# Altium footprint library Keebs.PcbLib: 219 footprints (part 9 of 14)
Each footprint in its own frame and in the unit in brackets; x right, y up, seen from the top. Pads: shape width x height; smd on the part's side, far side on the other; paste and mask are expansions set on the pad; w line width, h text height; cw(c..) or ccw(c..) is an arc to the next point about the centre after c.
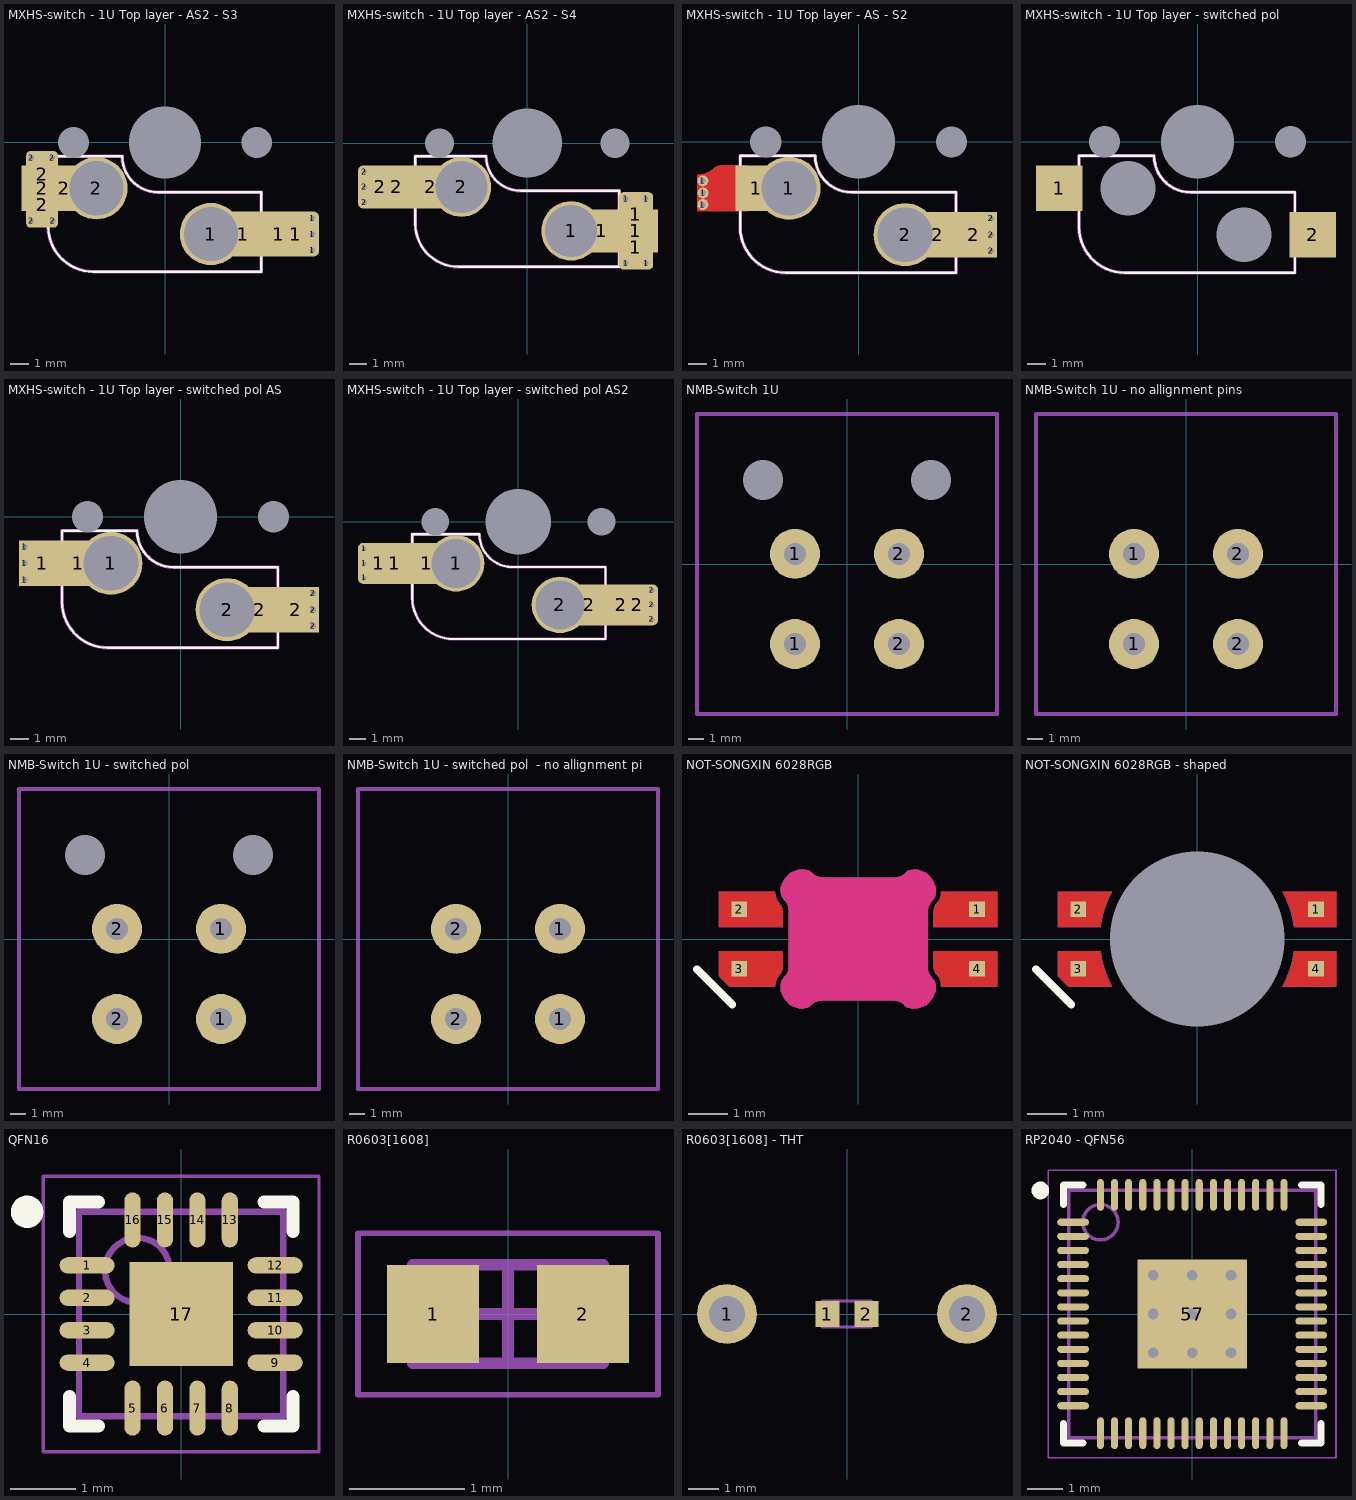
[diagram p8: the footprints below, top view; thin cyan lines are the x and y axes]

## MXHS-switch - 1U Top layer - AS2 - S3 [mm]
pads (19):
  round 3.45 hole 3 mask+0: 1(2.54,-5.08) 2(-3.81,-2.54)
  rect 2.55x2.5 smd paste-40 mask+0.102: 1(4.318,-5.08) 2(-5.588,-2.54)
  rect 2.55x2.5 smd: 1(6.29,-5.08)
  rrect25% 2.55x2.5 smd paste-40 mask+0.102: 1(7.25,-5.08)
  round 0.6 hole 0.3 mask+0.102: 1(8.15,-5.969) 1(8.15,-5.08) 1(8.15,-4.191) 2(-7.412,-4.349) 2(-7.412,-0.858) 2(-6.25,-0.858) 2(-6.234,-4.349)
  rrect25% 1.75x2.55 smd paste-40 mask+0.102: 2(-6.823,-3.449) 2(-6.823,-1.758)
  rect 2.3x2.5 smd: 2(-6.8,-2.54)
  round 1 hole 1.7 unplated: ""(-5.08,0) ""(5.08,0)
  round 1 hole 4 unplated: ""(0,0)
Top Overlay:
  lines w0.127: -6.481,-4.662 ccw(c-3.981,-4.662) -3.981,-7.162 5.319,-7.162 5.319,-2.762 -0.381,-2.762 cw(c-0.381,-0.762) -2.381,-0.762 -6.481,-0.762 -6.481,-4.662
Mechanical 13:
  lines w0.1: -0.5,0 0.5,0 ; 0,-0.5 0,0.5
  lines w0.2: -6.481,-4.662 ccw(c-3.981,-4.662) -3.981,-7.162 5.319,-7.162 5.319,-2.762 -0.381,-2.762 cw(c-0.381,-0.762) -2.381,-0.762 -6.481,-0.762 -6.481,-4.662
  text ".Designator" at 3.048,-4.826 h0.7
Mechanical 15:
  lines w0.1: -1.77,0 -0.77,0 ; 0,-0.5 0,0.5
  lines w0.127: -6.481,-4.662 ccw(c-3.981,-4.662) -3.981,-7.162 5.319,-7.162 5.319,-2.762 -0.381,-2.762 cw(c-0.381,-0.762) -2.381,-0.762 -6.481,-0.762 -6.481,-4.662
3D body "kailh_socket_mx.stp": height -0.35, standoff -3.4, extent -7.9,-6.745 6.6,-0.855

## MXHS-switch - 1U Top layer - AS2 - S4 [mm]
pads (19):
  round 3.45 hole 3 mask+0: 1(2.54,-5.08) 2(-3.81,-2.54)
  rect 2.55x2.5 smd paste-40 mask+0.102: 1(4.318,-5.08) 2(-5.588,-2.54)
  round 0.6 hole 0.3 mask+0.102: 1(5.701,-6.94) 1(5.701,-3.22) 1(6.879,-6.94) 1(6.879,-3.22) 2(-9.42,-3.429) 2(-9.42,-2.54) 2(-9.42,-1.651)
  rrect25% 2x2.55 smd paste-40 mask+0.102: 1(6.29,-6.04) 1(6.29,-4.12)
  rect 2.55x2.5 smd: 1(6.29,-5.08) 2(-7.56,-2.54)
  rrect25% 2.55x2.5 smd paste-40 mask+0.102: 2(-8.52,-2.54)
  round 1 hole 1.7 unplated: ""(-5.08,0) ""(5.08,0)
  round 1 hole 4 unplated: ""(0,0)
Top Overlay:
  lines w0.127: -6.481,-4.662 ccw(c-3.981,-4.662) -3.981,-7.162 5.319,-7.162 5.319,-2.762 -0.381,-2.762 cw(c-0.381,-0.762) -2.381,-0.762 -6.481,-0.762 -6.481,-4.662
Mechanical 13:
  lines w0.1: -0.5,0 0.5,0 ; 0,-0.5 0,0.5
  lines w0.2: -6.481,-4.662 ccw(c-3.981,-4.662) -3.981,-7.162 5.319,-7.162 5.319,-2.762 -0.381,-2.762 cw(c-0.381,-0.762) -2.381,-0.762 -6.481,-0.762 -6.481,-4.662
  text ".Designator" at 3.048,-4.826 h0.7
Mechanical 15:
  lines w0.1: -1.77,0 -0.77,0 ; 0,-0.5 0,0.5
  lines w0.127: -6.481,-4.662 ccw(c-3.981,-4.662) -3.981,-7.162 5.319,-7.162 5.319,-2.762 -0.381,-2.762 cw(c-0.381,-0.762) -2.381,-0.762 -6.481,-0.762 -6.481,-4.662
3D body "kailh_socket_mx.stp": height -0.35, standoff -3.4, extent -7.9,-6.745 6.6,-0.855

## MXHS-switch - 1U Top layer - AS - S2 [mm] "Adjusted footprint to prevent conflict with tray mount mounting hole"
pads (14):
  round 0.6 hole 0.3 mask+0.102: 1(-8.52,-3.429) 1(-8.52,-2.134) 1(-8.509,-2.794) 2(7.25,-5.969) 2(7.25,-5.08) 2(7.25,-4.191)
  rect 2.3x2.492 smd paste-40 mask+0.102: 1(-5.588,-2.54)
  round 3.45 hole 3 mask+0: 1(-3.81,-2.54) 2(2.54,-5.08)
  rect 2.55x2.5 smd paste-40 mask+0.102: 2(4.318,-5.08)
  rect 2.55x2.5 smd: 2(6.29,-5.08)
  round 1 hole 1.7 unplated: ""(-5.08,0) ""(5.08,0)
  round 1 hole 4 unplated: ""(0,0)
Top Layer:
  region: -6.096,-1.295 -6.096,-3.785 -8.839,-3.785 -8.839,-1.905 -8.839,-1.88 -8.82,-1.833 -8.784,-1.797 -8.737,-1.778 -8.712,-1.778 -8.606,-1.773 -8.398,-1.731 -8.201,-1.65 -8.025,-1.532 -7.946,-1.46 -7.906,-1.421 -7.814,-1.36 -7.712,-1.317 -7.603,-1.295 -7.547,-1.295
Top Overlay:
  lines w0.127: -6.481,-4.662 ccw(c-3.981,-4.662) -3.981,-7.162 5.319,-7.162 5.319,-2.762 -0.381,-2.762 cw(c-0.381,-0.762) -2.381,-0.762 -6.481,-0.762 -6.481,-4.662
Mechanical 13:
  lines w0.1: -0.5,0 0.5,0 ; 0,-0.5 0,0.5
  lines w0.2: -6.481,-4.662 ccw(c-3.981,-4.662) -3.981,-7.162 5.319,-7.162 5.319,-2.762 -0.381,-2.762 cw(c-0.381,-0.762) -2.381,-0.762 -6.481,-0.762 -6.481,-4.662
  text ".Designator" at 3.048,-4.826 h0.7
Mechanical 15:
  lines w0.1: -1.77,0 -0.77,0 ; 0,-0.5 0,0.5
  lines w0.127: -6.481,-4.662 ccw(c-3.981,-4.662) -3.981,-7.162 5.319,-7.162 5.319,-2.762 -0.381,-2.762 cw(c-0.381,-0.762) -2.381,-0.762 -6.481,-0.762 -6.481,-4.662
3D body "kailh_socket_mx.stp": height -0.35, standoff -3.4, extent -7.9,-6.745 6.6,-0.855

## MXHS-switch - 1U Top layer - switched pol [mm]
pads (7):
  rect 2.55x2.5 smd: 1(-7.56,-2.54) 2(6.29,-5.08)
  round 1 hole 1.7 unplated: ""(-5.08,0) ""(5.08,0)
  round 0 hole 3 unplated: ""(-3.81,-2.54) ""(2.54,-5.08)
  round 1 hole 4 unplated: ""(0,0)
Top Overlay:
  lines w0.127: -6.481,-4.662 ccw(c-3.981,-4.662) -3.981,-7.162 5.319,-7.162 5.319,-2.762 -0.381,-2.762 cw(c-0.381,-0.762) -2.381,-0.762 -6.481,-0.762 -6.481,-4.662
Mechanical 13:
  lines w0.1: -0.5,0 0.5,0 ; 0,-0.5 0,0.5
  lines w0.2: -6.481,-4.662 ccw(c-3.981,-4.662) -3.981,-7.162 5.319,-7.162 5.319,-2.762 -0.381,-2.762 cw(c-0.381,-0.762) -2.381,-0.762 -6.481,-0.762 -6.481,-4.662
  text ".Designator" at 3.048,-4.826 h0.7
Mechanical 15:
  lines w0.1: -1.77,0 -0.77,0 ; 0,-0.5 0,0.5
  lines w0.127: -6.481,-4.662 ccw(c-3.981,-4.662) -3.981,-7.162 5.319,-7.162 5.319,-2.762 -0.381,-2.762 cw(c-0.381,-0.762) -2.381,-0.762 -6.481,-0.762 -6.481,-4.662
3D body "kailh_socket_mx.stp": height -0.35, standoff -3.4, extent -7.9,-6.745 6.6,-0.855

## MXHS-switch - 1U Top layer - switched pol AS [mm]
pads (15):
  round 0.6 hole 0.3 mask+0.102: 1(-8.52,-3.429) 1(-8.52,-2.54) 1(-8.52,-1.651) 2(7.25,-5.969) 2(7.25,-5.08) 2(7.25,-4.191)
  rect 2.55x2.5 smd: 1(-7.56,-2.54) 2(6.29,-5.08)
  rect 2.55x2.5 smd paste-40 mask+0.102: 1(-5.588,-2.54) 2(4.318,-5.08)
  round 3.45 hole 3 mask+0: 1(-3.81,-2.54) 2(2.54,-5.08)
  round 1 hole 1.7 unplated: ""(-5.08,0) ""(5.08,0)
  round 1 hole 4 unplated: ""(0,0)
Top Overlay:
  lines w0.127: -6.481,-4.662 ccw(c-3.981,-4.662) -3.981,-7.162 5.319,-7.162 5.319,-2.762 -0.381,-2.762 cw(c-0.381,-0.762) -2.381,-0.762 -6.481,-0.762 -6.481,-4.662
Mechanical 13:
  lines w0.1: -0.5,0 0.5,0 ; 0,-0.5 0,0.5
  lines w0.2: -6.481,-4.662 ccw(c-3.981,-4.662) -3.981,-7.162 5.319,-7.162 5.319,-2.762 -0.381,-2.762 cw(c-0.381,-0.762) -2.381,-0.762 -6.481,-0.762 -6.481,-4.662
  text ".Designator" at 3.048,-4.826 h0.7
Mechanical 15:
  lines w0.1: -1.77,0 -0.77,0 ; 0,-0.5 0,0.5
  lines w0.127: -6.481,-4.662 ccw(c-3.981,-4.662) -3.981,-7.162 5.319,-7.162 5.319,-2.762 -0.381,-2.762 cw(c-0.381,-0.762) -2.381,-0.762 -6.481,-0.762 -6.481,-4.662
3D body "kailh_socket_mx.stp": height -0.35, standoff -3.4, extent -7.9,-6.745 6.6,-0.855

## MXHS-switch - 1U Top layer - switched pol AS2 [mm]
pads (17):
  round 0.6 hole 0.3 mask+0.102: 1(-9.42,-3.429) 1(-9.42,-2.54) 1(-9.42,-1.651) 2(8.15,-5.969) 2(8.15,-5.08) 2(8.15,-4.191)
  rrect25% 2.55x2.5 smd paste-40 mask+0.102: 1(-8.52,-2.54) 2(7.25,-5.08)
  rect 2.55x2.5 smd: 1(-7.56,-2.54) 2(6.29,-5.08)
  rect 2.55x2.5 smd paste-40 mask+0.102: 1(-5.588,-2.54) 2(4.318,-5.08)
  round 3.45 hole 3 mask+0: 1(-3.81,-2.54) 2(2.54,-5.08)
  round 1 hole 1.7 unplated: ""(-5.08,0) ""(5.08,0)
  round 1 hole 4 unplated: ""(0,0)
Top Overlay:
  lines w0.127: -6.481,-4.662 ccw(c-3.981,-4.662) -3.981,-7.162 5.319,-7.162 5.319,-2.762 -0.381,-2.762 cw(c-0.381,-0.762) -2.381,-0.762 -6.481,-0.762 -6.481,-4.662
Mechanical 13:
  lines w0.1: -0.5,0 0.5,0 ; 0,-0.5 0,0.5
  lines w0.2: -6.481,-4.662 ccw(c-3.981,-4.662) -3.981,-7.162 5.319,-7.162 5.319,-2.762 -0.381,-2.762 cw(c-0.381,-0.762) -2.381,-0.762 -6.481,-0.762 -6.481,-4.662
  text ".Designator" at 3.048,-4.826 h0.7
Mechanical 15:
  lines w0.1: -1.77,0 -0.77,0 ; 0,-0.5 0,0.5
  lines w0.127: -6.481,-4.662 ccw(c-3.981,-4.662) -3.981,-7.162 5.319,-7.162 5.319,-2.762 -0.381,-2.762 cw(c-0.381,-0.762) -2.381,-0.762 -6.481,-0.762 -6.481,-4.662
3D body "kailh_socket_mx.stp": height -0.35, standoff -3.4, extent -7.9,-6.745 6.6,-0.855

## NMB-Switch 1U [mm]
pads (7):
  round 3.18 hole 1.4 mask+0.102: 1(-3.3,-5.08) 1(-3.3,0.64) 2(3.3,-5.08) 2(3.3,0.64)
  round 0 hole 2.54 unplated mask+0.102: ""(-5.33,5.33) ""(5.33,5.33)
  round 1 on Mech13: ""(0,0)
Mechanical 13:
  lines w0.254: -9.525,-9.525 -9.525,9.525 9.525,9.525 9.525,-9.525 -9.525,-9.525
  text ".Designator" at -3.575,-3.7 h0.7

## NMB-Switch 1U - no allignment pins [mm]
pads (5):
  round 3.18 hole 1.4 mask+0.102: 1(-3.3,-5.08) 1(-3.3,0.64) 2(3.3,-5.08) 2(3.3,0.64)
  round 1 on Mech13: ""(0,0)
Mechanical 13:
  lines w0.254: -9.525,-9.525 -9.525,9.525 9.525,9.525 9.525,-9.525 -9.525,-9.525
  text ".Designator" at -3.575,-3.7 h0.7

## NMB-Switch 1U - switched pol [mm]
pads (7):
  round 3.18 hole 1.4 mask+0.102: 1(3.3,-5.08) 1(3.3,0.64) 2(-3.3,-5.08) 2(-3.3,0.64)
  round 0 hole 2.54 unplated mask+0.102: ""(-5.33,5.33) ""(5.33,5.33)
  round 1 on Mech13: ""(0,0)
Mechanical 13:
  lines w0.254: -9.525,-9.525 9.525,-9.525 9.525,9.525 -9.525,9.525 -9.525,-9.525
  text ".Designator" at -3.575,-3.7 h0.7

## NMB-Switch 1U - switched pol  - no allignment pins [mm]
pads (5):
  round 3.18 hole 1.4 mask+0.102: 1(3.3,-5.08) 1(3.3,0.64) 2(-3.3,-5.08) 2(-3.3,0.64)
  round 1 on Mech13: ""(0,0)
Mechanical 13:
  lines w0.254: -9.525,-9.525 9.525,-9.525 9.525,9.525 -9.525,9.525 -9.525,-9.525
  text ".Designator" at -3.575,-3.7 h0.7

## NOT-SONGXIN 6028RGB [mm] "Uncommon Anode reverse mount LED"
pads (4):
  rect 0.4x0.4 smd: 1(3,0.75) 2(-3,0.75) 3(-3,-0.75) 4(3,-0.75)
Top Layer:
  region: -3.5,0.304 -3.5,1.195 -2.1,1.195 -2.1,1.172 -2.098,1.13 -2.082,1.048 -2.05,0.97 -2.003,0.901 -1.975,0.869 -1.957,0.852 -1.929,0.81 -1.91,0.763 -1.9,0.714 -1.9,0.688 -1.9,0.304
  region: -3.25,-1.195 -3.5,-0.945 -3.5,-0.304 -1.9,-0.304 -1.9,-0.702 -1.9,-0.727 -1.91,-0.776 -1.929,-0.823 -1.957,-0.865 -1.975,-0.883 -2.003,-0.914 -2.05,-0.984 -2.082,-1.061 -2.098,-1.143 -2.1,-1.185 -2.1,-1.195
  region: 1.975,-0.883 1.957,-0.865 1.929,-0.823 1.91,-0.776 1.9,-0.727 1.9,-0.702 1.9,-0.304 3.5,-0.304 3.5,-1.195 2.1,-1.195 2.1,-1.185 2.098,-1.143 2.082,-1.061 2.05,-0.984 2.003,-0.914
  region: 1.9,0.702 1.9,0.727 1.91,0.776 1.929,0.823 1.957,0.865 1.975,0.883 2.003,0.914 2.05,0.984 2.082,1.061 2.098,1.143 2.1,1.185 2.1,1.195 3.5,1.195 3.5,0.304 1.9,0.304
  pour cut-out: -1.95,-1.2 -1.95,-1.198 -1.95,-1.195 -1.95,-1.192 -1.949,-1.188 -1.949,-1.187 -1.949,-1.185 -1.95,-1.182 -1.95,-1.178 -1.95,-1.175 -1.95,-1.173 -1.95,-1.143 -1.939,-1.085 -1.916,-1.029 -1.882,-0.979 -1.861,-0.958 -1.836,-0.93 -1.794,-0.868 -1.765,-0.798 -1.751,-0.725 -1.749,-0.687 -1.749,0.714 -1.751,0.751 -1.765,0.825 -1.794,0.894 -1.836,0.957 -1.861,0.985 -1.882,1.006 -1.916,1.056 -1.939,1.111 -1.95,1.17 -1.95,1.2 -1.95,1.309 -1.867,1.512 -1.712,1.667 -1.509,1.75 -1.4,1.75 -1.373,1.75 -1.343,1.75 -1.285,1.739 -1.229,1.716 -1.179,1.682 -1.158,1.661 -1.13,1.636 -1.068,1.594 -0.998,1.565 -0.925,1.551 -0.887,1.549 0.914,1.549 0.951,1.551 1.025,1.565 1.094,1.594 1.157,1.636 1.185,1.661 1.206,1.682 1.256,1.716 1.311,1.739 1.37,1.75 1.4,1.75 1.509,1.75 1.712,1.667 1.867,1.512 1.95,1.309 1.95,1.2 1.95,1.198 1.95,1.195 1.95,1.192 1.949,1.188 1.949,1.187 1.949,1.185 1.95,1.182 1.95,1.178 1.95,1.175 1.95,1.173 1.95,1.143 1.939,1.085 1.916,1.029 1.882,0.979 1.861,0.958 1.836,0.93 1.794,0.868 1.765,0.798 1.751,0.725 1.749,0.687 1.749,-0.714 1.751,-0.751 1.765,-0.825 1.794,-0.894 1.836,-0.957 1.861,-0.985 1.882,-1.006 1.916,-1.056 1.939,-1.111 1.95,-1.17 1.95,-1.2 1.95,-1.309 1.867,-1.512 1.712,-1.667 1.509,-1.75 1.4,-1.75 1.398,-1.75 1.395,-1.75 1.392,-1.75 1.388,-1.749 1.387,-1.749 1.385,-1.749 1.382,-1.75 1.378,-1.75 1.375,-1.75 1.373,-1.75 1.343,-1.75 1.285,-1.739 1.229,-1.716 1.179,-1.682 1.158,-1.661 1.13,-1.636 1.068,-1.594 0.998,-1.565 0.925,-1.551 0.887,-1.549 -0.914,-1.549 -0.951,-1.551 -1.025,-1.565 -1.094,-1.594 -1.157,-1.636 -1.185,-1.661 -1.206,-1.682 -1.256,-1.716 -1.311,-1.739 -1.37,-1.75 -1.4,-1.75 -1.509,-1.75 -1.712,-1.667 -1.867,-1.512 -1.95,-1.309
Bottom Layer:
  pour cut-out: -1.95,-1.2 -1.95,-1.198 -1.95,-1.195 -1.95,-1.192 -1.949,-1.188 -1.949,-1.187 -1.949,-1.185 -1.95,-1.182 -1.95,-1.178 -1.95,-1.175 -1.95,-1.173 -1.95,-1.143 -1.939,-1.085 -1.916,-1.029 -1.882,-0.979 -1.861,-0.958 -1.836,-0.93 -1.794,-0.868 -1.765,-0.798 -1.751,-0.725 -1.749,-0.687 -1.749,0.714 -1.751,0.751 -1.765,0.825 -1.794,0.894 -1.836,0.957 -1.861,0.985 -1.882,1.006 -1.916,1.056 -1.939,1.111 -1.95,1.17 -1.95,1.2 -1.95,1.309 -1.867,1.512 -1.712,1.667 -1.509,1.75 -1.4,1.75 -1.373,1.75 -1.343,1.75 -1.285,1.739 -1.229,1.716 -1.179,1.682 -1.158,1.661 -1.13,1.636 -1.068,1.594 -0.998,1.565 -0.925,1.551 -0.887,1.549 0.914,1.549 0.951,1.551 1.025,1.565 1.094,1.594 1.157,1.636 1.185,1.661 1.206,1.682 1.256,1.716 1.311,1.739 1.37,1.75 1.4,1.75 1.509,1.75 1.712,1.667 1.867,1.512 1.95,1.309 1.95,1.2 1.95,1.198 1.95,1.195 1.95,1.192 1.949,1.188 1.949,1.187 1.949,1.185 1.95,1.182 1.95,1.178 1.95,1.175 1.95,1.173 1.95,1.143 1.939,1.085 1.916,1.029 1.882,0.979 1.861,0.958 1.836,0.93 1.794,0.868 1.765,0.798 1.751,0.725 1.749,0.687 1.749,-0.714 1.751,-0.751 1.765,-0.825 1.794,-0.894 1.836,-0.957 1.861,-0.985 1.882,-1.006 1.916,-1.056 1.939,-1.111 1.95,-1.17 1.95,-1.2 1.95,-1.309 1.867,-1.512 1.712,-1.667 1.509,-1.75 1.4,-1.75 1.398,-1.75 1.395,-1.75 1.392,-1.75 1.388,-1.749 1.387,-1.749 1.385,-1.749 1.382,-1.75 1.378,-1.75 1.375,-1.75 1.373,-1.75 1.343,-1.75 1.285,-1.739 1.229,-1.716 1.179,-1.682 1.158,-1.661 1.13,-1.636 1.068,-1.594 0.998,-1.565 0.925,-1.551 0.887,-1.549 -0.914,-1.549 -0.951,-1.551 -1.025,-1.565 -1.094,-1.594 -1.157,-1.636 -1.185,-1.661 -1.206,-1.682 -1.256,-1.716 -1.311,-1.739 -1.37,-1.75 -1.4,-1.75 -1.509,-1.75 -1.712,-1.667 -1.867,-1.512 -1.95,-1.309
Top Overlay:
  lines w0.2: -4.064,-0.762 -3.175,-1.651
Keep-Out Layer:
  board cut-out: -1.95,-1.2 -1.95,-1.198 -1.95,-1.195 -1.95,-1.192 -1.949,-1.188 -1.949,-1.187 -1.949,-1.185 -1.95,-1.182 -1.95,-1.178 -1.95,-1.175 -1.95,-1.173 -1.95,-1.143 -1.939,-1.085 -1.916,-1.029 -1.882,-0.979 -1.861,-0.958 -1.836,-0.93 -1.794,-0.868 -1.765,-0.798 -1.751,-0.725 -1.749,-0.687 -1.749,0.714 -1.751,0.751 -1.765,0.825 -1.794,0.894 -1.836,0.957 -1.861,0.985 -1.882,1.006 -1.916,1.056 -1.939,1.111 -1.95,1.17 -1.95,1.2 -1.95,1.309 -1.867,1.512 -1.712,1.667 -1.509,1.75 -1.4,1.75 -1.373,1.75 -1.343,1.75 -1.285,1.739 -1.229,1.716 -1.179,1.682 -1.158,1.661 -1.13,1.636 -1.068,1.594 -0.998,1.565 -0.925,1.551 -0.887,1.549 0.914,1.549 0.951,1.551 1.025,1.565 1.094,1.594 1.157,1.636 1.185,1.661 1.206,1.682 1.256,1.716 1.311,1.739 1.37,1.75 1.4,1.75 1.509,1.75 1.712,1.667 1.867,1.512 1.95,1.309 1.95,1.2 1.95,1.198 1.95,1.195 1.95,1.192 1.949,1.188 1.949,1.187 1.949,1.185 1.95,1.182 1.95,1.178 1.95,1.175 1.95,1.173 1.95,1.143 1.939,1.085 1.916,1.029 1.882,0.979 1.861,0.958 1.836,0.93 1.794,0.868 1.765,0.798 1.751,0.725 1.749,0.687 1.749,-0.714 1.751,-0.751 1.765,-0.825 1.794,-0.894 1.836,-0.957 1.861,-0.985 1.882,-1.006 1.916,-1.056 1.939,-1.111 1.95,-1.17 1.95,-1.2 1.95,-1.309 1.867,-1.512 1.712,-1.667 1.509,-1.75 1.4,-1.75 1.398,-1.75 1.395,-1.75 1.392,-1.75 1.388,-1.749 1.387,-1.749 1.385,-1.749 1.382,-1.75 1.378,-1.75 1.375,-1.75 1.373,-1.75 1.343,-1.75 1.285,-1.739 1.229,-1.716 1.179,-1.682 1.158,-1.661 1.13,-1.636 1.068,-1.594 0.998,-1.565 0.925,-1.551 0.887,-1.549 -0.914,-1.549 -0.951,-1.551 -1.025,-1.565 -1.094,-1.594 -1.157,-1.636 -1.185,-1.661 -1.206,-1.682 -1.256,-1.716 -1.311,-1.739 -1.37,-1.75 -1.4,-1.75 -1.509,-1.75 -1.712,-1.667 -1.867,-1.512 -1.95,-1.309
Mechanical 1:
  lines w0.1: -1.9,-1.2 ccw(c-1.4,-1.2) -1.4,-1.7 ccw(c-1.4,-1.446) -1.22,-1.626 cw(c-0.914,-1.932) -0.914,-1.499 0.887,-1.499 cw(c0.887,-1.932) 1.194,-1.626 ccw(c1.373,-1.446) 1.373,-1.7 ; -1.9,-1.173 cw(c-1.646,-1.173) -1.826,-0.994 ccw(c-2.132,-0.687) -1.699,-0.687 -1.699,0.714 ccw(c-2.132,0.714) -1.826,1.02 cw(c-1.646,1.2) -1.9,1.2 cw(c-1.4,1.2) -1.4,1.7 -1.373,1.7 cw(c-1.373,1.446) -1.194,1.626 ccw(c-0.887,1.932) -0.887,1.499 0.914,1.499 ccw(c0.914,1.932) 1.22,1.626 cw(c1.4,1.446) 1.4,1.7 cw(c1.4,1.2) 1.9,1.2 ; 1.4,-1.7 ccw(c1.4,-1.2) 1.9,-1.2 ccw(c1.646,-1.2) 1.826,-1.02 cw(c2.132,-0.714) 1.699,-0.714 1.699,0.687 cw(c2.132,0.687) 1.826,0.994 ccw(c1.646,1.173) 1.9,1.173
Mechanical 7:
  lines w0.01: -2.1,1.172 ccw(c-1.672,1.172) -1.975,0.869 cw(c-2.156,0.688) -1.9,0.688 -1.9,0.618 -1.9,0.304 -2.449,0.304 -3.455,0.304 -3.5,0.304 -3.5,0.349 -3.5,1.154 -3.5,1.195 -2.1,1.195 -2.1,1.175 ; 3.5,-1.195 2.1,-1.195 2.1,-1.185 ccw(c1.672,-1.185) 1.975,-0.883 cw(c2.156,-0.702) 1.9,-0.702 1.9,-0.618 1.9,-0.304 2.449,-0.304 3.455,-0.304 3.5,-0.304 ; 3.5,-1.195 3.5,-1.154 ; 3.5,-1.195 3.5,-1.154 ; 3.5,-1.154 3.5,-0.349 ; 3.5,-1.154 3.5,-0.349 ; 3.5,-0.349 3.5,-0.304 ; 3.5,-0.349 3.5,-0.304 ; 3.5,0.304 3.455,0.304 2.449,0.304 1.9,0.304 1.9,0.618 1.9,0.702 cw(c2.156,0.702) 1.975,0.883 ccw(c1.672,1.185) 2.1,1.185 2.1,1.195 3.5,1.195 ; 3.5,0.304 3.5,0.349 ; 3.5,0.304 3.5,0.349 ; 3.5,0.349 3.5,1.154 ; 3.5,0.349 3.5,1.154 ; 3.5,1.154 3.5,1.195 ; 3.5,1.154 3.5,1.195 ; -3.5,-0.945 -3.25,-1.195 -2.464,-1.195 -2.1,-1.195 -2.1,-1.185 cw(c-1.672,-1.185) -1.975,-0.883 ccw(c-2.156,-0.702) -1.9,-0.702 -1.9,-0.618 -1.9,-0.304 -2.449,-0.304 -3.455,-0.304 -3.5,-0.304 -3.5,-0.945
Mechanical 13:
  lines w0.1: -1.6,-1.4 1.6,-1.4 1.6,1.4 -1.6,1.4 -1.6,-1.4
  text ".Designator" at -1.27,-0.127 h0.35
3D body "LED_SK6812MINI-E.step": height 0.94, standoff -0.84, extent -2.94,-1.403 2.94,1.397

## NOT-SONGXIN 6028RGB - shaped [mm] "Uncommon Anode reverse mount LED"
pads (5):
  rect 0.4x0.4 smd: 1(3,0.75) 2(-3,0.75) 3(-3,-0.75) 4(3,-0.75)
  round 1 hole 4.4 unplated: ""(0,0)
Top Layer:
  region: -3.25,-1.195 -3.5,-0.945 -3.5,-0.304 -2.449,-0.304 -2.447,-0.304 -2.43,-0.421 -2.378,-0.651 -2.305,-0.875 -2.211,-1.091 -2.157,-1.195
  region: 2.157,-1.195 3.5,-1.195 3.5,-0.304 2.449,-0.304 2.447,-0.304 2.43,-0.421 2.378,-0.651 2.305,-0.875 2.211,-1.091
  region: 2.447,0.304 2.43,0.421 2.378,0.651 2.305,0.875 2.211,1.091 2.157,1.195 3.5,1.195 3.5,0.304
  region: -3.5,0.304 -3.5,1.195 -2.157,1.195 -2.211,1.091 -2.305,0.875 -2.378,0.651 -2.43,0.421 -2.447,0.304 -2.449,0.304
Top Overlay:
  lines w0.2: -4.064,-0.762 -3.175,-1.651
Mechanical 7:
  lines w0.01: -2.449,-0.304 -3.455,-0.304 -3.5,-0.304 -3.5,-0.945 -3.25,-1.195 -2.211,-1.195 -2.157,-1.195 cw(c0,0) -2.447,-0.304 ; -2.449,0.304 -3.455,0.304 -3.5,0.304 -3.5,0.349 -3.5,1.154 -3.5,1.195 -3.476,1.195 -2.211,1.195 -2.157,1.195 ccw(c0,0) -2.447,0.304 ; 2.447,-0.304 cw(c0,0) 2.157,-1.195 2.211,-1.195 3.476,-1.195 3.5,-1.195 3.5,-1.154 3.5,-0.349 3.5,-0.304 3.455,-0.304 2.449,-0.304 ; 2.447,0.304 ccw(c0,0) 2.157,1.195 2.211,1.195 3.476,1.195 3.5,1.195 3.5,1.154 3.5,0.349 3.5,0.304 3.455,0.304 2.449,0.304
Mechanical 13:
  lines w0.1: -1.6,-1.4 1.6,-1.4 1.6,1.4 -1.6,1.4 -1.6,-1.4
  text ".Designator" at -1.27,-0.127 h0.35
3D body "LED_SK6812MINI-E.step": height 0.94, standoff -0.84, extent -2.94,-1.403 2.94,1.397

## QFN16 [mm] "Generated for BQ24075RGTR"
height 1
pads (17):
  oval 0.85x0.25 smd: 1(-1.45,0.75) 2(-1.45,0.25) 3(-1.45,-0.25) 4(-1.45,-0.75) 9(1.45,-0.75) 10(1.45,-0.25) 11(1.45,0.25) 12(1.45,0.75)
  oval 0.25x0.85 smd: 5(-0.75,-1.45) 6(-0.25,-1.45) 7(0.25,-1.45) 8(0.75,-1.45) 13(0.75,1.45) 14(0.25,1.45) 15(-0.25,1.45) 16(-0.75,1.45)
  rect 1.6x1.6 smd: 17(0,0)
Top Overlay:
  circle w0.25: c-2.375,1.575 r0.125
  lines w0.2: -1.725,-1.275 -1.725,-1.725 -1.275,-1.725 ; -1.725,1.275 -1.725,1.725 -1.275,1.725 ; 1.275,-1.725 1.725,-1.725 1.725,-1.275 ; 1.275,1.725 1.725,1.725 1.725,1.275
Mechanical 13:
  circle w0.1: c-0.675,0.675 r0.5
  lines w0.1: -1.575,-1.575 1.575,-1.575 1.575,1.575 -1.575,1.575 -1.575,-1.575
  text ".Designator" at -0.991,-1.067 h0.35
Mechanical 15:
  lines w0.05: -2.125,-2.125 2.125,-2.125 2.125,2.125 -2.125,2.125 -2.125,-2.125
  lines w0.1: -0.5,0 0.5,0 ; 0,-0.5 0,0.5
3D body "QFN16.step": height 1, standoff 0, extent -1.655,-1.655 1.655,1.655

## R0603[1608] [mm] "Chip Resistor, 2-Leads, Body 1,57x0,80mm, IPC Medium Density"
height 0.5
pads (2):
  rect 0.8x0.85 smd: 1(-0.65,0) 2(0.65,0)
Mechanical 13:
  lines w0.1: -0.825,-0.425 0.825,-0.425 0.825,0.425 -0.825,0.425 -0.825,-0.425
  text ".Designator" at -1.05,-0.275 h0.35
Mechanical 15:
  lines w0.05: -1.3,-0.7 1.3,-0.7 1.3,0.7 -1.3,0.7 -1.3,-0.7
  lines w0.1: -0.425,0 0.425,0 ; 0,-0.425 0,0.425
3D body: height 0.5, standoff 0, extent -0.525,-0.425 0.525,0.425
3D body: height 0.5, standoff 0, extent 0.525,-0.425 0.825,0.425
3D body: height 0.5, standoff 0, extent -0.825,-0.425 -0.525,0.425

## R0603[1608] - THT [mm] "Chip Resistor, 2-Leads, Body 1,57x0,80mm, IPC Medium Density"
height 0.5
pads (4):
  round 2 hole 1.2: 1(-4,0) 2(4,0)
  rect 0.8x0.85 smd paste-6: 1(-0.65,0) 2(0.65,0)
Mechanical 13:
  lines w0.1: -0.825,-0.425 0.825,-0.425 0.825,0.425 -0.825,0.425 -0.825,-0.425
  text ".Designator" at -0.635,-0.127 h0.35

## RP2040 - QFN56 [mm]
height 0.9
pads (57):
  oval 0.9x0.2 smd: 1(-3.375,2.6) 2(-3.375,2.2) 3(-3.375,1.8) 4(-3.375,1.4) 5(-3.375,1) 6(-3.375,0.6) 7(-3.375,0.2) 8(-3.375,-0.2) 9(-3.375,-0.6) 10(-3.375,-1) 11(-3.375,-1.4) 12(-3.375,-1.8) 13(-3.375,-2.2) 14(-3.375,-2.6) 29(3.375,-2.6) 30(3.375,-2.2) 31(3.375,-1.8) 32(3.375,-1.4) 33(3.375,-1) 34(3.375,-0.6) 35(3.375,-0.2) 36(3.375,0.2) 37(3.375,0.6) 38(3.375,1) 39(3.375,1.4) 40(3.375,1.8) 41(3.375,2.2) 42(3.375,2.6)
  oval 0.2x0.9 smd: 15(-2.6,-3.375) 16(-2.2,-3.375) 17(-1.8,-3.375) 18(-1.4,-3.375) 19(-1,-3.375) 20(-0.6,-3.375) 21(-0.2,-3.375) 22(0.2,-3.375) 23(0.6,-3.375) 24(1,-3.375) 25(1.4,-3.375) 26(1.8,-3.375) 27(2.2,-3.375) 28(2.6,-3.375) 43(2.6,3.375) 44(2.2,3.375) 45(1.8,3.375) 46(1.4,3.375) 47(1,3.375) 48(0.6,3.375) 49(0.2,3.375) 50(-0.2,3.375) 51(-0.6,3.375) 52(-1,3.375) 53(-1.4,3.375) 54(-1.8,3.375) 55(-2.2,3.375) 56(-2.6,3.375)
  rect 3.1x3.1 smd: 57(0,0)
via -1.1,1.1 diameter 0.6 hole 0.3
via 0,1.1 diameter 0.6 hole 0.3
via 1.1,1.1 diameter 0.6 hole 0.3
via -1.1,0 diameter 0.6 hole 0.3
via 0,0 diameter 0.6 hole 0.3
via 1.1,0 diameter 0.6 hole 0.3
via -1.1,-1.1 diameter 0.6 hole 0.3
via 0,-1.1 diameter 0.6 hole 0.3
via 1.1,-1.1 diameter 0.6 hole 0.3
Top Overlay:
  circle w0.25: c-4.3,3.5 r0.125
  lines w0.2: -3.65,-3.1 -3.65,-3.65 -3.1,-3.65 ; -3.65,3.1 -3.65,3.65 -3.1,3.65 ; 3.1,-3.65 3.65,-3.65 3.65,-3.1 ; 3.1,3.65 3.65,3.65 3.65,3.1
Mechanical 13:
  circle w0.1: c-2.6,2.6 r0.5
  lines w0.1: -3.5,-3.5 -3.5,3.5 3.5,3.5 3.5,-3.5 -3.5,-3.5
  text ".Designator" at -1.586,-0.17 h0.35
Mechanical 15:
  lines w0.05: -4.075,-4.075 -4.075,4.075 4.075,4.075 4.075,-4.075 -4.075,-4.075
  lines w0.1: -0.5,0 0.5,0 ; 0,-0.5 0,0.5
3D body "RP2040 - QFN56.step": height 0.9, standoff 0, extent -3.51,-3.51 3.51,3.51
